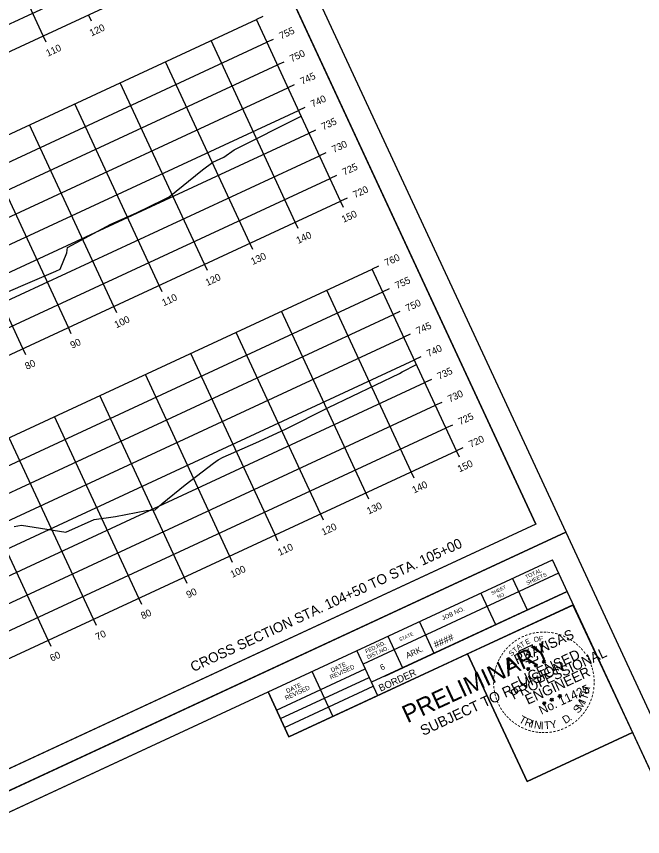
# Model space of a CAD drawing. Extents: x 1354696 to 1366163, y 660729 to 670380.
# Drawn here: x 1356792.7 to 1356917.8, y 665117.7 to 665281.6 of the extents above; entities that cross this region are included whole.
import ezdxf

# ---------------------------------------------------------------- set-up
doc = ezdxf.new("R2010")
doc.units = 0
for name, color, linetype in [('R_Axis', 7, 'Continuous'), ('R_Axis Annot', 7, 'Continuous'), ('R_Border', 7, 'Continuous'), ('R_Border PE', 7, 'Continuous'), ('R_Border Prem', 7, 'Continuous'), ('R_Draft', 7, 'Continuous'), ('R_Exist Surface', 7, 'Continuous'), ('R_Grid', 7, 'Continuous'), ('R_No Plot', 7, 'Continuous')]:
    doc.layers.add(name, color=color, linetype=linetype)

msp = doc.modelspace()

# ---------------------------------------------------------------- linework, layer by layer
at = {"layer": 'R_Axis'}
for p, q in [((1356562.19, 665168.25), (1356834.29, 665294.59)), ((1356807.67, 665280.68), (1356807.08, 665281.95)), ((1356841.88, 665281.57), (1356840.61, 665280.98)), ((1356857.45, 665244.7), (1356840.61, 665280.98)), ((1356798.6, 665276.47), (1356798.01, 665277.74)), ((1356843.98, 665277.03), (1356842.71, 665276.44)), ((1356846.09, 665272.5), (1356844.82, 665271.91)), ((1356848.19, 665267.96), (1356846.92, 665267.37)), ((1356850.3, 665263.43), (1356849.03, 665262.84)), ((1356852.4, 665258.89), (1356851.14, 665258.3)), ((1356854.51, 665254.36), (1356853.24, 665253.77)), ((1356856.62, 665249.82), (1356855.35, 665249.23)), ((1356585.35, 665118.37), (1356857.45, 665244.7)), ((1356858.72, 665245.29), (1356857.45, 665244.7)), ((1356858.04, 665243.43), (1356857.45, 665244.7)), ((1356848.97, 665239.22), (1356848.38, 665240.49)), ((1356839.9, 665235.01), (1356839.31, 665236.28)), ((1356830.83, 665230.8), (1356830.24, 665232.07)), ((1356865.04, 665231.68), (1356863.77, 665231.09)), ((1356880.61, 665194.81), (1356863.77, 665231.09)), ((1356821.76, 665226.59), (1356821.17, 665227.86)), ((1356867.14, 665227.15), (1356865.87, 665226.56)), ((1356812.69, 665222.37), (1356812.1, 665223.64)), ((1356869.25, 665222.61), (1356867.98, 665222.02)), ((1356803.62, 665218.16), (1356803.03, 665219.43)), ((1356871.35, 665218.08), (1356870.08, 665217.49)), ((1356794.55, 665213.95), (1356793.96, 665215.22)), ((1356873.46, 665213.54), (1356872.19, 665212.95)), ((1356875.57, 665209.01), (1356874.3, 665208.42)), ((1356877.67, 665204.47), (1356876.4, 665203.88)), ((1356879.78, 665199.94), (1356878.51, 665199.35)), ((1356608.51, 665068.48), (1356880.61, 665194.81)), ((1356881.88, 665195.4), (1356880.61, 665194.81)), ((1356881.2, 665193.54), (1356880.61, 665194.81)), ((1356872.13, 665189.33), (1356871.54, 665190.6)), ((1356863.06, 665185.12), (1356862.47, 665186.39)), ((1356853.99, 665180.91), (1356853.4, 665182.18)), ((1356844.92, 665176.7), (1356844.33, 665177.97)), ((1356835.85, 665172.49), (1356835.26, 665173.76)), ((1356826.78, 665168.28), (1356826.19, 665169.55)), ((1356817.71, 665164.07), (1356817.12, 665165.34)), ((1356808.64, 665159.86), (1356808.05, 665161.13)), ((1356799.57, 665155.64), (1356798.98, 665156.91))]:
    msp.add_line(p, q, dxfattribs=at)
at = {"layer": 'R_Border'}
for p, q in [((1356896.45, 665180.12), (1356809.93, 665366.47)), ((1356896.45, 665180.12), (1356609.67, 665046.97)), ((1356612.99, 665039.83), (1356899.77, 665172.97)), ((1356986.29, 664986.62), (1356899.77, 665172.97)), ((1356901.01, 665170.31), (1356861.92, 665152.16)), ((1356901, 665170.32), (1356901, 665170.32)), ((1356891.79, 665169.27), (1356894.71, 665162.97)), ((1356902.69, 665166.68), (1356863.6, 665148.53)), ((1356866.29, 665149.77), (1356902.69, 665166.68)), ((1356885.49, 665166.34), (1356888.42, 665160.05)), ((1356903.93, 665164.01), (1356847.12, 665137.63)), ((1356873.18, 665160.63), (1356876.1, 665154.33)), ((1356866.88, 665157.7), (1356869.81, 665151.41)), ((1356860.68, 665154.82), (1356864.84, 665145.86)), ((1356844.65, 665142.95), (1356862.37, 665151.18)), ((1356855.9, 665141.71), (1356851.74, 665150.67)), ((1356845.43, 665141.26), (1356863.15, 665149.49)), ((1356846.25, 665139.5), (1356863.97, 665147.73)), ((1356847.12, 665137.63), (1356842.96, 665146.59))]:
    msp.add_line(p, q, dxfattribs=at)
at = {"layer": 'R_Border PE'}
for p, q in [((1356896.45, 665151.88), (1356896.3, 665152.21)), ((1356896.3, 665152.21), (1356896.45, 665152)), ((1356896.3, 665152.21), (1356896.36, 665151.96)), ((1356896.72, 665152.12), (1356896.45, 665151.88)), ((1356896.72, 665152.12), (1356896.48, 665151.96)), ((1356896.72, 665152.12), (1356896.58, 665151.94)), ((1356897.69, 665152.56), (1356897.94, 665152.63)), ((1356897.69, 665152.56), (1356898.05, 665152.61)), ((1356897.69, 665152.56), (1356897.96, 665152.55)), ((1356898.05, 665152.61), (1356897.9, 665152.94)), ((1356897.9, 665152.94), (1356898.05, 665152.73)), ((1356897.9, 665152.94), (1356897.97, 665152.69)), ((1356897.98, 665152.25), (1356898.05, 665152.61)), ((1356897.98, 665152.25), (1356898.09, 665152.54)), ((1356897.98, 665152.25), (1356898, 665152.52)), ((1356898.32, 665152.86), (1356898.05, 665152.61)), ((1356898.37, 665152.43), (1356898.05, 665152.61)), ((1356898.32, 665152.86), (1356898.08, 665152.69)), ((1356898.37, 665152.43), (1356898.09, 665152.53)), ((1356898.37, 665152.43), (1356898.13, 665152.64)), ((1356898.32, 665152.86), (1356898.18, 665152.68)), ((1356894.57, 665151.13), (1356894.82, 665151.19)), ((1356894.57, 665151.13), (1356894.93, 665151.17)), ((1356894.57, 665151.13), (1356894.84, 665151.12)), ((1356894.93, 665151.17), (1356894.78, 665151.5)), ((1356894.78, 665151.5), (1356894.93, 665151.3)), ((1356894.78, 665151.5), (1356894.85, 665151.26)), ((1356894.86, 665150.81), (1356894.93, 665151.17)), ((1356894.86, 665150.81), (1356894.97, 665151.1)), ((1356894.86, 665150.81), (1356894.88, 665151.09)), ((1356895.2, 665151.42), (1356894.93, 665151.17)), ((1356895.25, 665150.99), (1356894.93, 665151.17)), ((1356895.2, 665151.42), (1356894.96, 665151.26)), ((1356895.25, 665150.99), (1356894.97, 665151.1)), ((1356895.25, 665150.99), (1356895.01, 665151.2)), ((1356895.2, 665151.42), (1356895.06, 665151.24)), ((1356896.09, 665151.83), (1356896.33, 665151.9)), ((1356896.09, 665151.83), (1356896.45, 665151.88)), ((1356896.09, 665151.83), (1356896.35, 665151.82)), ((1356896.38, 665151.52), (1356896.45, 665151.88)), ((1356896.38, 665151.52), (1356896.48, 665151.8)), ((1356896.38, 665151.52), (1356896.39, 665151.79)), ((1356896.77, 665151.7), (1356896.45, 665151.88)), ((1356896.77, 665151.7), (1356896.48, 665151.8)), ((1356896.77, 665151.7), (1356896.52, 665151.9)), ((1356900.88, 665145.69), (1356901.13, 665145.76)), ((1356900.88, 665145.69), (1356901.24, 665145.74)), ((1356900.88, 665145.69), (1356901.14, 665145.68)), ((1356901.24, 665145.74), (1356901.09, 665146.07)), ((1356901.09, 665146.07), (1356901.24, 665145.87)), ((1356901.09, 665146.07), (1356901.16, 665145.83)), ((1356901.17, 665145.38), (1356901.24, 665145.74)), ((1356901.17, 665145.38), (1356901.27, 665145.67)), ((1356901.17, 665145.38), (1356901.18, 665145.65)), ((1356901.51, 665145.99), (1356901.24, 665145.74)), ((1356901.56, 665145.56), (1356901.24, 665145.74)), ((1356901.51, 665145.99), (1356901.27, 665145.82)), ((1356901.56, 665145.56), (1356901.27, 665145.66)), ((1356901.56, 665145.56), (1356901.31, 665145.77)), ((1356901.51, 665145.99), (1356901.37, 665145.81)), ((1356897.76, 665144.26), (1356898.01, 665144.32)), ((1356897.76, 665144.26), (1356898.12, 665144.3)), ((1356897.76, 665144.26), (1356898.02, 665144.25)), ((1356898.12, 665144.3), (1356897.97, 665144.63)), ((1356897.97, 665144.63), (1356898.12, 665144.43)), ((1356897.97, 665144.63), (1356898.04, 665144.39)), ((1356898.05, 665143.94), (1356898.12, 665144.3)), ((1356898.05, 665143.94), (1356898.15, 665144.23)), ((1356898.05, 665143.94), (1356898.06, 665144.22)), ((1356898.39, 665144.55), (1356898.12, 665144.3)), ((1356898.44, 665144.12), (1356898.12, 665144.3)), ((1356898.39, 665144.55), (1356898.15, 665144.38)), ((1356898.44, 665144.12), (1356898.15, 665144.23)), ((1356898.44, 665144.12), (1356898.19, 665144.33)), ((1356898.39, 665144.55), (1356898.25, 665144.37)), ((1356899.27, 665144.96), (1356899.52, 665145.03)), ((1356899.27, 665144.96), (1356899.63, 665145.01)), ((1356899.27, 665144.96), (1356899.54, 665144.95)), ((1356899.63, 665145.01), (1356899.48, 665145.34)), ((1356899.48, 665145.34), (1356899.63, 665145.13)), ((1356899.48, 665145.34), (1356899.55, 665145.09)), ((1356899.56, 665144.65), (1356899.63, 665145.01)), ((1356899.56, 665144.65), (1356899.67, 665144.93)), ((1356899.56, 665144.65), (1356899.57, 665144.92)), ((1356899.9, 665145.25), (1356899.63, 665145.01)), ((1356899.95, 665144.83), (1356899.63, 665145.01)), ((1356899.9, 665145.25), (1356899.66, 665145.09)), ((1356899.95, 665144.83), (1356899.67, 665144.93)), ((1356899.95, 665144.83), (1356899.71, 665145.03)), ((1356899.9, 665145.25), (1356899.76, 665145.07))]:
    msp.add_line(p, q, dxfattribs=at)
for points in [[(1356896.55, 665155.3), (1356896.56, 665155.62), (1356895.95, 665155.31), (1356895.8, 665155.97), (1356892.98, 665154.66)], [(1356892.98, 665154.66), (1356893.57, 665154.02)], [(1356894.44, 665152.67), (1356894.48, 665152.59), (1356895, 665152.81), (1356895.15, 665152.36), (1356896.84, 665153.15), (1356896.8, 665153.72)], [(1356896.3, 665152.21), (1356896.77, 665151.7), (1356896.09, 665151.83), (1356896.72, 665152.12), (1356896.38, 665151.52), (1356896.3, 665152.21)], [(1356897.9, 665152.94), (1356898.37, 665152.43), (1356897.69, 665152.56), (1356898.32, 665152.86), (1356897.98, 665152.25), (1356897.9, 665152.94)], [(1356894.78, 665151.5), (1356895.25, 665150.99), (1356894.57, 665151.13), (1356895.2, 665151.42), (1356894.86, 665150.81), (1356894.78, 665151.5)], [(1356901.09, 665146.07), (1356901.56, 665145.56), (1356900.88, 665145.69), (1356901.51, 665145.99), (1356901.17, 665145.38), (1356901.09, 665146.07)], [(1356897.97, 665144.63), (1356898.44, 665144.12), (1356897.76, 665144.26), (1356898.39, 665144.55), (1356898.05, 665143.94), (1356897.97, 665144.63)], [(1356899.48, 665145.34), (1356899.95, 665144.83), (1356899.27, 665144.96), (1356899.9, 665145.25), (1356899.56, 665144.65), (1356899.48, 665145.34)]]:
    msp.add_lwpolyline(points, dxfattribs=at)
for centre, radius in [((1356898.05, 665152.61), 0.172), ((1356898.05, 665152.61), 0.145), ((1356898.05, 665152.61), 0.116), ((1356898.05, 665152.61), 0.0991), ((1356898.05, 665152.61), 0.0747), ((1356898.05, 665152.61), 0.0495), ((1356898.05, 665152.61), 0.0296), ((1356894.93, 665151.17), 0.172), ((1356894.93, 665151.17), 0.145), ((1356894.93, 665151.17), 0.116), ((1356894.93, 665151.17), 0.0991), ((1356894.93, 665151.17), 0.0747), ((1356894.93, 665151.17), 0.0495), ((1356894.93, 665151.17), 0.0296), ((1356896.45, 665151.88), 0.172), ((1356896.45, 665151.88), 0.145), ((1356896.45, 665151.88), 0.116), ((1356896.45, 665151.88), 0.0991), ((1356896.45, 665151.88), 0.0747), ((1356896.45, 665151.88), 0.0495), ((1356896.45, 665151.88), 0.0296), ((1356901.24, 665145.74), 0.172), ((1356901.24, 665145.74), 0.145), ((1356901.24, 665145.74), 0.116), ((1356901.24, 665145.74), 0.0991), ((1356901.24, 665145.74), 0.0747), ((1356901.24, 665145.74), 0.0495), ((1356901.24, 665145.74), 0.0296), ((1356898.12, 665144.3), 0.172), ((1356898.12, 665144.3), 0.145), ((1356898.12, 665144.3), 0.116), ((1356898.12, 665144.3), 0.0991), ((1356898.12, 665144.3), 0.0747), ((1356898.12, 665144.3), 0.0495), ((1356898.12, 665144.3), 0.0296), ((1356899.63, 665145), 0.172), ((1356899.63, 665145), 0.145), ((1356899.63, 665145), 0.116), ((1356899.63, 665145), 0.0991), ((1356899.63, 665145), 0.0747), ((1356899.63, 665145), 0.0495), ((1356899.63, 665145), 0.0296)]:
    msp.add_circle(centre, radius, dxfattribs=at)
at = {"layer": 'R_Exist Surface'}
for points in [[(1356779.63, 665221.7), (1356794, 665227.91), (1356800.5, 665230.7), (1356801.38, 665231.08), (1356802.7, 665234.36), (1356802.83, 665235.41), (1356811.54, 665240.06), (1356816.64, 665242.36), (1356821.97, 665244.92), (1356823.17, 665245.52), (1356829.86, 665250.92), (1356831.92, 665252.46), (1356834.08, 665253.5), (1356836.15, 665254.92), (1356849.56, 665261.7)], [(1356792.19, 665179.68), (1356793.66, 665179.9), (1356802.52, 665178.51), (1356808.16, 665181.05), (1356812.45, 665181.66), (1356818.62, 665182.83), (1356820.41, 665182.98), (1356821.78, 665184.28), (1356826.37, 665187.99), (1356832.02, 665192.31), (1356832.98, 665192.97), (1356834, 665193.5), (1356840.5, 665196.4), (1356846.44, 665199.11), (1356855, 665203.43), (1356869.23, 665210.24), (1356869.75, 665210.59), (1356872.61, 665212.04)]]:
    msp.add_lwpolyline(points, dxfattribs=at)
at = {"layer": 'R_Grid'}
for p, q in [((1356798.01, 665277.74), (1356781.17, 665314.02)), ((1356560.08, 665172.79), (1356832.19, 665299.12)), ((1356562.19, 665168.25), (1356834.29, 665294.59)), ((1356568.5, 665154.65), (1356840.61, 665280.98)), ((1356857.45, 665244.7), (1356840.61, 665280.98)), ((1356848.38, 665240.49), (1356831.54, 665276.77)), ((1356570.61, 665150.11), (1356842.71, 665276.44)), ((1356572.71, 665145.58), (1356844.82, 665271.91)), ((1356839.31, 665236.28), (1356822.47, 665272.56)), ((1356574.82, 665141.04), (1356846.92, 665267.37)), ((1356830.24, 665232.07), (1356813.4, 665268.35)), ((1356821.17, 665227.86), (1356804.33, 665264.14)), ((1356576.93, 665136.51), (1356849.03, 665262.84)), ((1356812.1, 665223.64), (1356795.26, 665259.92)), ((1356579.03, 665131.97), (1356851.14, 665258.3)), ((1356803.03, 665219.43), (1356786.19, 665255.71)), ((1356581.14, 665127.44), (1356853.24, 665253.77)), ((1356793.96, 665215.22), (1356777.12, 665251.5)), ((1356583.24, 665122.9), (1356855.35, 665249.23)), ((1356585.35, 665118.37), (1356857.45, 665244.7)), ((1356591.66, 665104.76), (1356863.77, 665231.09)), ((1356880.61, 665194.81), (1356863.77, 665231.09)), ((1356593.77, 665100.23), (1356865.87, 665226.56)), ((1356871.54, 665190.6), (1356854.7, 665226.88)), ((1356862.47, 665186.39), (1356845.63, 665222.67)), ((1356595.88, 665095.69), (1356867.98, 665222.02)), ((1356853.4, 665182.18), (1356836.56, 665218.46)), ((1356597.98, 665091.16), (1356870.08, 665217.49)), ((1356600.09, 665086.62), (1356872.19, 665212.95)), ((1356844.33, 665177.97), (1356827.49, 665214.25)), ((1356835.26, 665173.76), (1356818.42, 665210.04)), ((1356602.19, 665082.09), (1356874.3, 665208.42)), ((1356826.19, 665169.55), (1356809.35, 665205.83)), ((1356604.3, 665077.55), (1356876.4, 665203.88)), ((1356817.12, 665165.34), (1356800.28, 665201.62)), ((1356606.4, 665073.02), (1356878.51, 665199.35)), ((1356808.05, 665161.13), (1356791.21, 665197.41)), ((1356608.51, 665068.48), (1356880.61, 665194.81)), ((1356798.98, 665156.91), (1356782.14, 665193.2))]:
    msp.add_line(p, q, dxfattribs=at)
at = {"layer": 'R_No Plot'}
for p, q in [((1356600.1, 665038.14), (1356902.44, 665178.51)), ((1356600.1, 665038.14), (1356902.44, 665178.51)), ((1356891.65, 665133.55), (1356891.65, 665133.55))]:
    msp.add_line(p, q, dxfattribs=at)
for points in [[(1356510.26, 665231.64), (1356812.6, 665372.01), (1356902.44, 665178.51), (1356600.1, 665038.14)], [(1356735.32, 665331.83), (1356753.12, 665340.1), (1356757.28, 665331.13), (1356771.89, 665337.92), (1356792.94, 665347.69), (1356804.9, 665322.2), (1356825.95, 665331.97), (1356896.45, 665180.12), (1356609.67, 665046.97), (1356523.15, 665233.33)], [(1356600.1, 665038.14), (1356902.44, 665178.51), (1356992.28, 664985.01), (1356689.93, 664844.64)], [(1356882.77, 665154.19), (1356903.82, 665163.96), (1356915.79, 665138.47), (1356894.74, 665128.7)], [(1356825.16, 665138.33), (1356842.96, 665146.59), (1356847.12, 665137.63), (1356861.73, 665144.42), (1356882.77, 665154.19), (1356894.74, 665128.7), (1356915.79, 665138.47), (1356986.29, 664986.62), (1356699.51, 664853.47), (1356612.99, 665039.83)]]:
    msp.add_lwpolyline(points, close=True, dxfattribs=at)

# ---------------------------------------------------------------- texts
at = {"layer": 'R_Axis Annot'}
for s, p in [('120', (1356807.65, 665277.59)), ('755', (1356845.55, 665276.99)), ('110', (1356798.94, 665273.54)), ('750', (1356847.65, 665272.45)), ('745', (1356849.76, 665267.92)), ('740', (1356851.86, 665263.38)), ('735', (1356853.97, 665258.85)), ('730', (1356856.07, 665254.31)), ('725', (1356858.18, 665249.78)), ('720', (1356860.29, 665245.24)), ('150', (1356858.03, 665240.34)), ('140', (1356848.96, 665236.12)), ('130', (1356839.89, 665231.91)), ('760', (1356866.6, 665231.64)), ('120', (1356830.81, 665227.7)), ('755', (1356868.71, 665227.1)), ('110', (1356822.1, 665223.66)), ('750', (1356870.81, 665222.57)), ('100', (1356812.62, 665219.26)), ('745', (1356872.92, 665218.03)), ('90', (1356803.81, 665215.17)), ('740', (1356875.02, 665213.5)), ('80', (1356794.74, 665210.96)), ('735', (1356877.13, 665208.96)), ('730', (1356879.24, 665204.43)), ('725', (1356881.34, 665199.89)), ('720', (1356883.45, 665195.36)), ('150', (1356881.19, 665190.45)), ('140', (1356872.12, 665186.24)), ('130', (1356863.05, 665182.03)), ('120', (1356853.98, 665177.82)), ('110', (1356845.27, 665173.77)), ('100', (1356835.79, 665169.37)), ('90', (1356826.98, 665165.28)), ('80', (1356817.91, 665161.07)), ('70', (1356808.83, 665156.86)), ('60', (1356799.73, 665152.63))]:
    msp.add_text(s, height=1.4, rotation=24.9042, dxfattribs=at).set_placement(p)
at = {"layer": 'R_Border'}
for s, height, p in [('TOTAL', 0.782, (1356894.54, 665169.13)), ('SHEETS', 0.782, (1356894.78, 665167.95)), ('SHEET', 0.684, (1356887.72, 665165.97)), ('NO.', 0.684, (1356888.93, 665165.22)), ('JOB NO.', 0.879, (1356877.91, 665160.88)), ('STATE', 0.684, (1356869.3, 665156.67)), ('####', 1.4, (1356876.42, 665155.3)), ('FED.RD.', 0.782, (1356862.56, 665154.29)), ('DIST.NO.', 0.782, (1356862.88, 665153.13)), ('ARK.', 1.172, (1356870.78, 665153.25)), ('DATE', 0.879, (1356855.71, 665150.46)), ('6', 1.17, (1356865.65, 665150.87)), ('REVISED', 0.879, (1356855.5, 665149.06)), ('BORDER', 1.4, (1356865.44, 665146.62)), ('REVISED', 0.879, (1356846.56, 665144.91)), ('DATE', 0.879, (1356846.77, 665146.31))]:
    msp.add_text(s, height=height, rotation=24.9042, dxfattribs=at).set_placement(p)
at = {"layer": 'R_Border PE'}
for s, height, rotation, p in [('ARKANSAS', 2, 24.9042, (1356891.08, 665151.26)), ('-', 1.6, 2.7593, (1356897.24, 665157.91)), ('-', 1.6, 359.0253, (1356897.92, 665157.93)), ('-', 1.6, 354.5451, (1356898.57, 665157.92)), ('-', 1.6, 35.1235, (1356892.49, 665156.12)), ('-', 1.6, 30.801, (1356893.11, 665156.53)), ('-', 1.6, 25.0904, (1356893.78, 665156.92)), ('-', 1.6, 22.6472, (1356894.44, 665157.21)), ('E', 1, 25.7365, (1356894.61, 665156.01)), ('-', 1.6, 17.0659, (1356895.14, 665157.48)), ('-', 1.6, 12.1091, (1356895.84, 665157.68)), ('O', 1, 15.3557, (1356896.15, 665156.5)), ('-', 1.6, 7.2404, (1356896.48, 665157.8)), ('F', 1, 4.9748, (1356897.11, 665156.69)), ('-', 1.6, 350.7668, (1356899.3, 665157.86)), ('-', 1.6, 345.4339, (1356900.04, 665157.73)), ('-', 1.6, 340.4828, (1356900.78, 665157.54)), ('-', 1.6, 334.7839, (1356901.53, 665157.28)), ('-', 1.6, 331.5563, (1356902.26, 665156.96)), ('-', 1.4, 328.5795, (1356902.94, 665156.64)), ('-', 1.6, 49.2114, (1356890.9, 665154.65)), ('-', 1.6, 44.0802, (1356891.37, 665155.16)), ('-', 1.6, 38.5343, (1356891.94, 665155.69)), ('T', 1, 41.3078, (1356892.31, 665154.36)), ('A', 1, 36.1173, (1356892.95, 665154.94)), ('T', 1, 30.9269, (1356893.65, 665155.45)), ('-', 1.6, 324.5725, (1356903.49, 665156.23)), ('-', 1.6, 319.567, (1356904.04, 665155.81)), ('-', 1.6, 315.477, (1356904.51, 665155.39)), ('-', 1.6, 310.0274, (1356904.97, 665154.97)), ('-', 1.6, 61.1359, (1356889.72, 665152.9)), ('-', 1.6, 58.9677, (1356890.08, 665153.5)), ('-', 1.6, 53.696, (1356890.46, 665154.09)), ('S', 1, 46.4982, (1356891.62, 665153.68)), ('PROFESSIONAL', 2, 24.9042, (1356891.98, 665145)), ('LICENSED', 2, 24.9042, (1356893.37, 665147.75)), ('-', 1.6, 305.4535, (1356905.47, 665154.38)), ('-', 1.6, 301.5003, (1356905.94, 665153.75)), ('-', 1.6, 67.8664, (1356889.23, 665151.8)), ('-', 1.6, 63.8548, (1356889.45, 665152.36)), ('DWB', 0.01, 24.9042, (1356898.04, 665152.6)), ('-', 1.6, 299.2343, (1356906.29, 665153.12)), ('-', 1.6, 294.8448, (1356906.59, 665152.56)), ('-', 1.6, 288.4214, (1356906.85, 665151.95)), ('-', 1.6, 79.1366, (1356888.73, 665149.88)), ('-', 1.6, 75.5183, (1356888.86, 665150.57)), ('-', 1.6, 73.3272, (1356889.02, 665151.18)), ('ENGINEER', 2, 24.9042, (1356894.86, 665144)), ('DWB', 0.01, 24.9042, (1356894.93, 665151.16)), ('DWB', 0.01, 24.9042, (1356896.44, 665151.87)), ('-', 1.6, 285.8995, (1356907.07, 665151.33)), ('-', 1.6, 280.6668, (1356907.25, 665150.67)), ('-', 1.6, 87.7755, (1356888.63, 665148.57)), ('-', 1.6, 82.9748, (1356888.66, 665149.26)), ('-', 1.6, 277.7723, (1356907.39, 665149.94)), ('-', 1.6, 272.7928, (1356907.47, 665149.23)), ('-', 1.6, 92.6784, (1356888.65, 665147.91)), ('-', 1.6, 97.2986, (1356888.72, 665147.25)), ('No. 11425', 1.757, 24.9042, (1356897.57, 665142)), ('H', 1.54, 79.513, (1356907.07, 665146.11)), ('-', 1.6, 263.9754, (1356907.46, 665147.7)), ('-', 1.6, 269.5239, (1356907.5, 665148.55)), ('-', 1.6, 100.3651, (1356888.84, 665146.52)), ('-', 1.6, 106.1054, (1356889.02, 665145.81)), ('-', 1.6, 110.0905, (1356889.24, 665145.16)), ('DWB', 0.01, 24.9042, (1356901.23, 665145.73)), ('T', 1.54, 71.5486, (1356906.66, 665144.88)), ('-', 1.6, 256.1579, (1356907.22, 665146.25)), ('-', 1.6, 258.7494, (1356907.37, 665146.94)), ('-', 1.6, 113.9664, (1356889.52, 665144.51)), ('-', 1.6, 119.1, (1356889.85, 665143.87)), ('DWB', 0.01, 24.9042, (1356898.11, 665144.29)), ('DWB', 0.01, 24.9042, (1356899.62, 665145)), ('S', 1.54, 51.8354, (1356904.95, 665142.18)), ('M', 1.54, 57.5605, (1356905.54, 665142.9)), ('I', 1.54, 67.0178, (1356906.35, 665144.21)), ('-', 1.6, 245.9893, (1356906.76, 665144.85)), ('-', 1.6, 250.6695, (1356907.02, 665145.53)), ('-', 1.6, 123.8521, (1356890.2, 665143.29)), ('-', 1.6, 126.6191, (1356890.63, 665142.68)), ('-', 1.6, 130.362, (1356891.03, 665142.21)), ('-', 1.6, 232.261, (1356905.78, 665143.07)), ('-', 1.6, 237.1533, (1356906.14, 665143.62)), ('-', 1.6, 240.6405, (1356906.46, 665144.19)), ('-', 1.6, 133.9916, (1356891.49, 665141.73)), ('-', 1.6, 138.9685, (1356891.97, 665141.3)), ('-', 1.6, 140.633, (1356892.51, 665140.87)), ('T', 1.54, 330.9447, (1356892.95, 665140.62)), ('R', 1.54, 338.9091, (1356894.08, 665139.99)), ('I', 1.54, 346.8735, (1356895.29, 665139.53)), ('N', 1.54, 351.4044, (1356896, 665139.34)), ('I', 1.54, 0.2645, (1356897.43, 665139.13)), ('T', 1.54, 4.7953, (1356898.17, 665139.11)), ('Y', 1.54, 12.7597, (1356899.46, 665139.22)), ('D', 1.54, 31.3011, (1356902.32, 665140.15)), ('.', 1.54, 38.6683, (1356903.35, 665140.77)), ('-', 1.6, 220.3785, (1356904.39, 665141.5)), ('-', 1.6, 225.6226, (1356904.9, 665142.01)), ('-', 1.6, 229.1558, (1356905.35, 665142.52)), ('-', 1.6, 145.3513, (1356893.08, 665140.48)), ('-', 1.6, 150.7976, (1356893.68, 665140.14)), ('-', 1.6, 155.6223, (1356894.33, 665139.84)), ('-', 1.6, 159.128, (1356895.03, 665139.56)), ('-', 1.6, 163.838, (1356895.7, 665139.36)), ('-', 1.6, 198.0196, (1356901.13, 665139.58)), ('-', 1.6, 201.4224, (1356901.83, 665139.85)), ('-', 1.6, 206.4959, (1356902.5, 665140.18)), ('-', 1.6, 210.7208, (1356903.2, 665140.59)), ('-', 1.6, 216.1899, (1356903.81, 665141.02)), ('-', 1.6, 169.5505, (1356896.38, 665139.23)), ('-', 1.6, 172.9939, (1356897.04, 665139.13)), ('-', 1.6, 176.4746, (1356897.7, 665139.08)), ('-', 1.6, 179.5044, (1356898.28, 665139.07)), ('-', 1.6, 183.4654, (1356898.95, 665139.11)), ('-', 1.6, 187.7024, (1356899.67, 665139.2)), ('-', 1.6, 192.4597, (1356900.38, 665139.35))]:
    msp.add_text(s, height=height, rotation=rotation, dxfattribs=at).set_placement(p)
at = {"layer": 'R_Border Prem'}
for s, height, p in [('PRELIMINARY', 3.5, (1356870.78, 665140.31)), ('SUBJECT TO REVISION', 2.0751, (1356873.95, 665137.78)), ('DWB', 0.01, (1356870.68, 665142.3))]:
    msp.add_text(s, height=height, rotation=24.9042, dxfattribs=at).set_placement(p)
at = {"layer": 'R_Draft'}
msp.add_text('CROSS SECTION STA. 104+50 TO STA. 105+00', height=2, rotation=24.9042, dxfattribs=at).set_placement((1356828, 665150.54))

doc.saveas('drawing.dxf')
